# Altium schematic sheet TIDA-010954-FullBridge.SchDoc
size 431 x 279 mm; Date: Not shown in title block; ApprovedBy: Not shown in title block; CheckedBy: Not shown in title block; Author: Not shown in title block; CompanyName: Not shown in title block; Engineer: Not shown in title block; Organization: Not shown in title block; Address1: Not shown in title block; Address2: Not shown in title block; Address3: Not shown in title block; Address4: Not shown in title block; DocumentNumber: 2; Revision: Use project parameter SCH_Rev; SheetNumber: 4; SheetTotal: 9; PageSetup: Record=PageOptions¦CenterHorizontal=True¦CenterVertical=True¦PrintScale=1.00¦XCorrection=1.00¦YCorrection=1.00¦PrintKind=0¦BorderSize=5000000¦LeftOffset=0¦BottomOffset=0¦Orientation=2¦PaperLength=1000¦PaperWidth=1000¦Scale=100¦PaperSource=15¦PrintQuality=600¦MediaType=1¦DitherType=10¦PaperKind=Letter¦PrintScaleMode=1
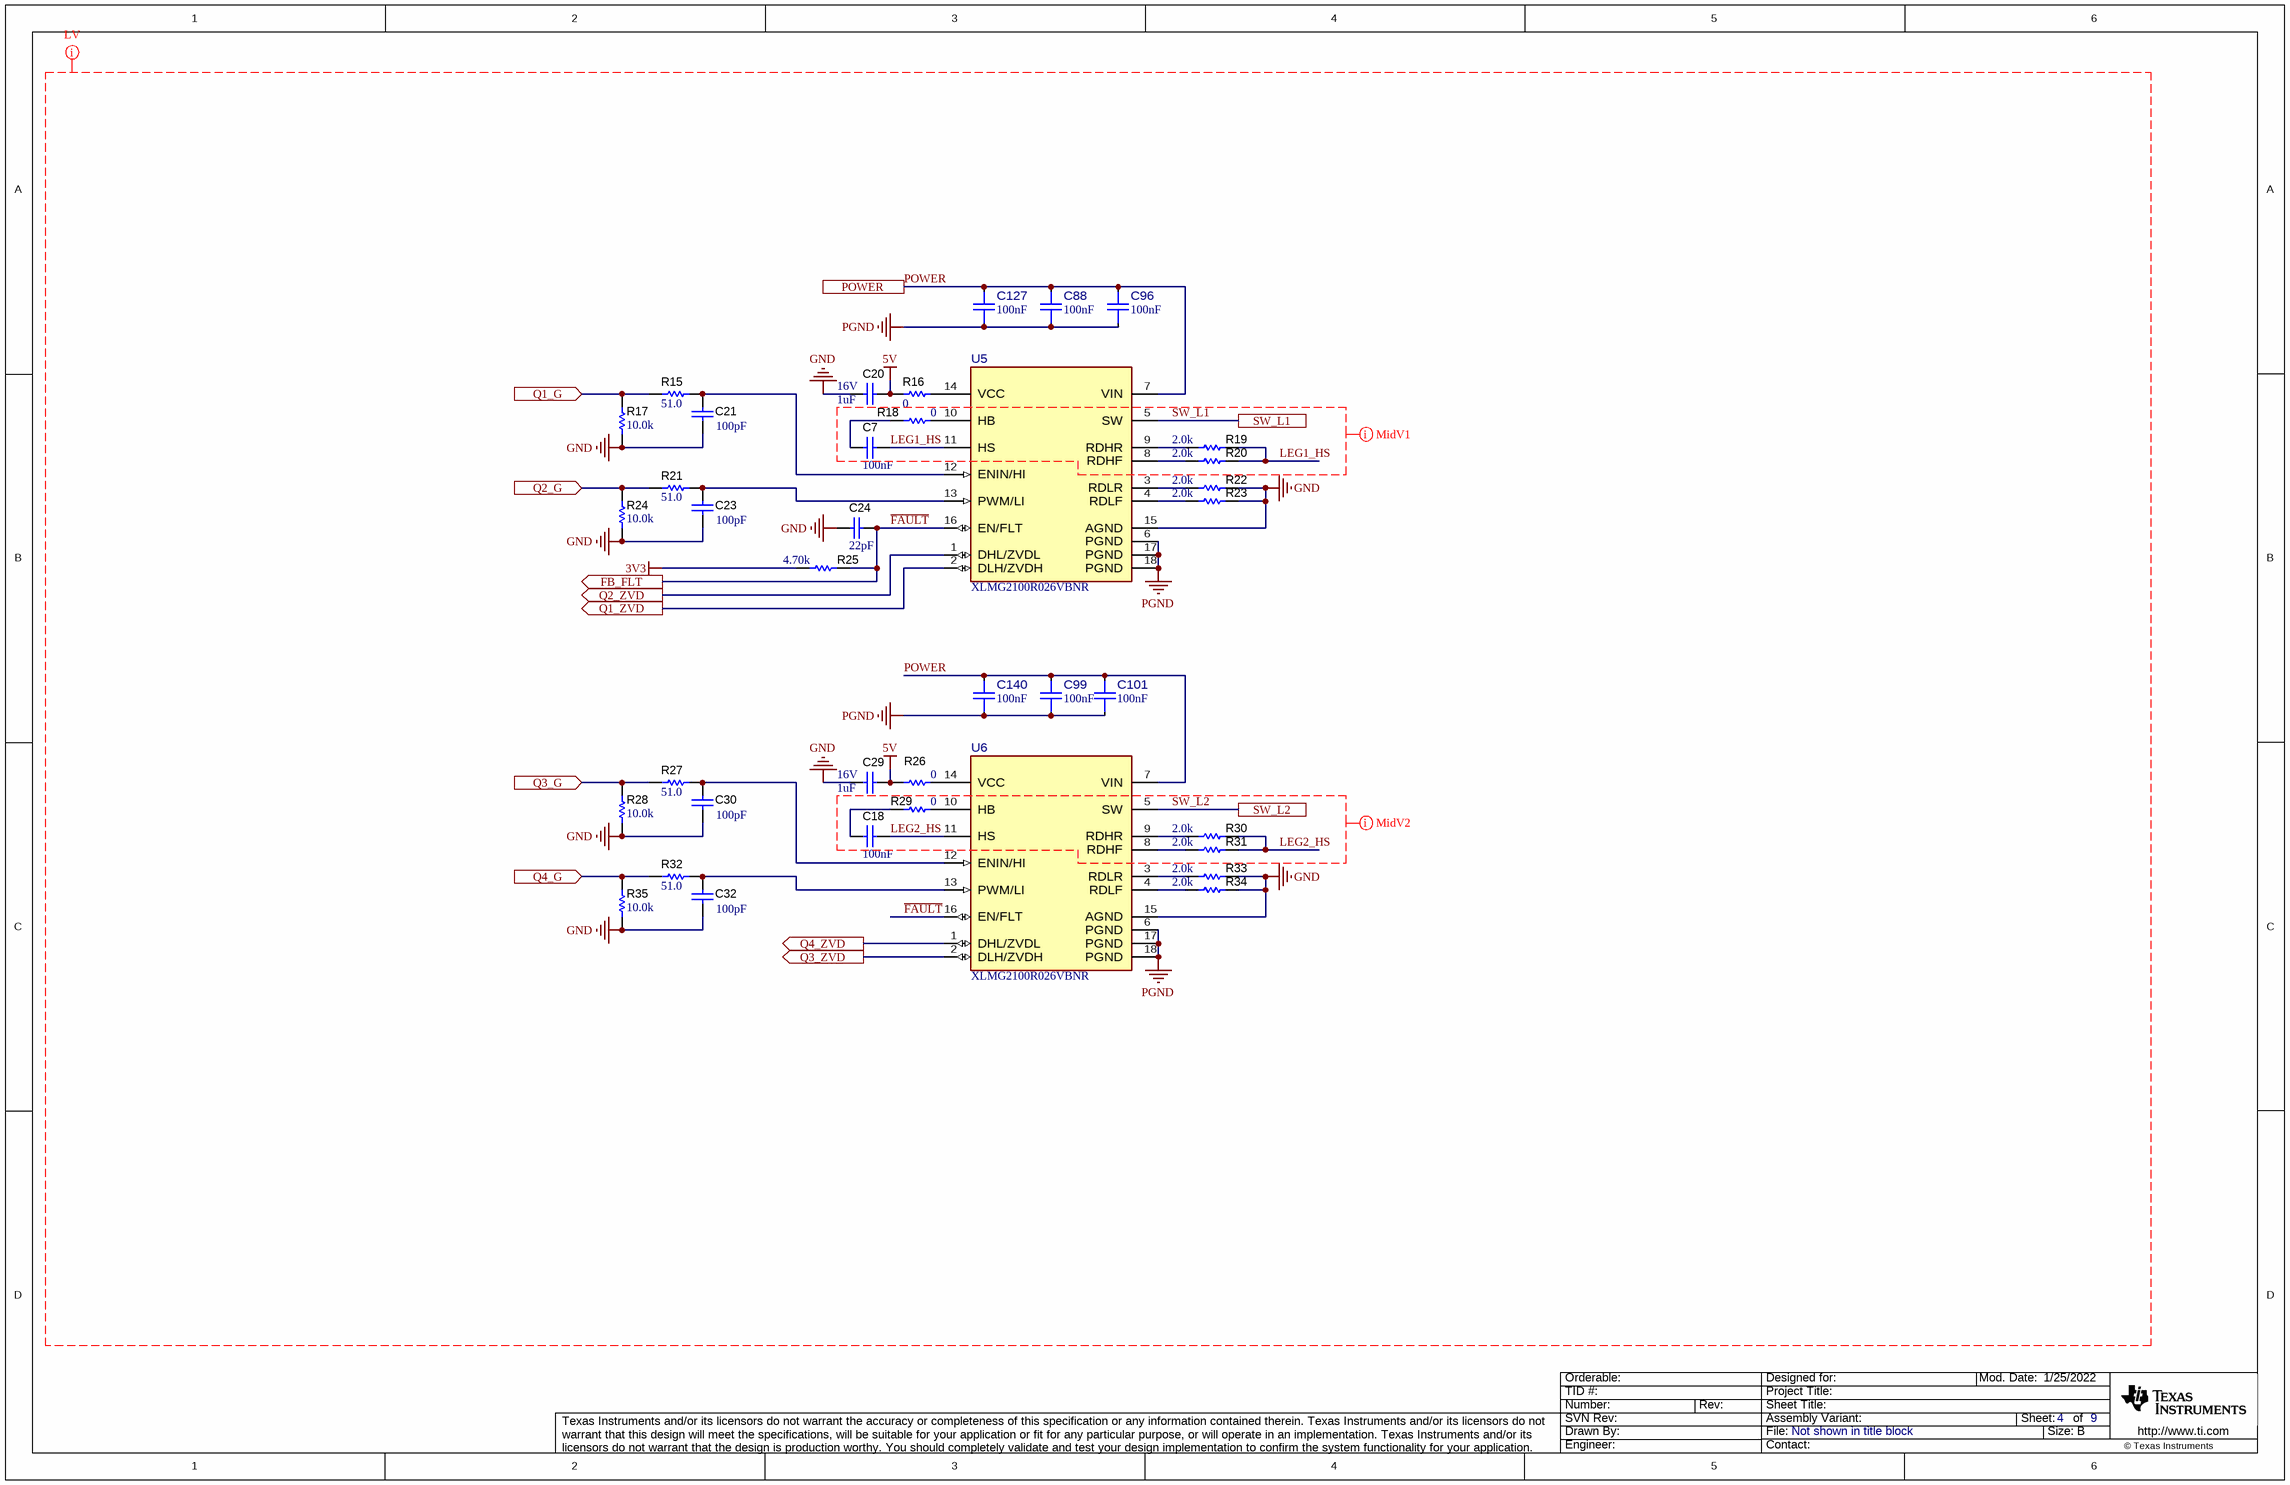
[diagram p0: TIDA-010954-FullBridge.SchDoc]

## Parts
C7  Cap_F: 100nF  [0603]  (hidden comment: CGA3E2X7R1E104K080AA)
C18  Cap_F: 100nF  [0603]  (hidden comment: CGA3E2X7R1E104K080AA)
C20  VDC_V: 16V  ValueDisplayed: 1uF  [0603]  (hidden comment: GRM185R61C105KE44D)
C21  ValueDisplayed: 100pF  [0603]  (hidden comment: GRM1885C1H101JA01D)
C23  ValueDisplayed: 100pF  [0603]  (hidden comment: GRM1885C1H101JA01D)
C24  ValueDisplayed: 22pF  [0603]  (hidden comment: GRM1885C1H220JA01D)
C29  VDC_V: 16V  ValueDisplayed: 1uF  [0603]  (hidden comment: GRM185R61C105KE44D)
C30  ValueDisplayed: 100pF  [0603]  (hidden comment: GRM1885C1H101JA01D)
C32  ValueDisplayed: 100pF  [0603]  (hidden comment: GRM1885C1H101JA01D)
C88  Cap_F: 100nF  [FP-GRM188R72A104KA35J_0603-MFG]  (hidden comment: GRM188R72A104KA35J)
C96  Cap_F: 100nF  [FP-GRM188R72A104KA35J_0603-MFG]  (hidden comment: GRM188R72A104KA35J)
C99  Cap_F: 100nF  [FP-GRM188R72A104KA35J_0603-MFG]  (hidden comment: GRM188R72A104KA35J)
C101  Cap_F: 100nF  [FP-GRM188R72A104KA35J_0603-MFG]  (hidden comment: GRM188R72A104KA35J)
C127  Cap_F: 100nF  [FP-GRM188R72A104KA35J_0603-MFG]  (hidden comment: GRM188R72A104KA35J)
C140  Cap_F: 100nF  [FP-GRM188R72A104KA35J_0603-MFG]  (hidden comment: GRM188R72A104KA35J)
R15  ValueDisplayed: 51.0  [0603]  (hidden comment: RC0603FR-0751RL)
R16  ValueDisplayed: 0  [0603]  (hidden comment: RC0603JR-070RL)
R17  ValueDisplayed: 10.0k  [0603]  (hidden comment: RC0603FR-0710KL)
R18  ValueDisplayed: 0  [0603]  (hidden comment: RC0603JR-070RL)
R19  ValueDisplayed: 2.0k  [0603]  (hidden comment: RC0603JR-072KL)
R20  ValueDisplayed: 2.0k  [0603]  (hidden comment: RC0603JR-072KL)
R21  ValueDisplayed: 51.0  [0603]  (hidden comment: RC0603FR-0751RL)
R22  ValueDisplayed: 2.0k  [0603]  (hidden comment: RC0603JR-072KL)
R23  ValueDisplayed: 2.0k  [0603]  (hidden comment: RC0603JR-072KL)
R24  ValueDisplayed: 10.0k  [0603]  (hidden comment: RC0603FR-0710KL)
R25  ValueDisplayed: 4.70k  [0603]  (hidden comment: RC0603FR-074K7L)
R26  ValueDisplayed: 0  [0603]  (hidden comment: RC0603JR-070RL)
R27  ValueDisplayed: 51.0  [0603]  (hidden comment: RC0603FR-0751RL)
R28  ValueDisplayed: 10.0k  [0603]  (hidden comment: RC0603FR-0710KL)
R29  ValueDisplayed: 0  [0603]  (hidden comment: RC0603JR-070RL)
R30  ValueDisplayed: 2.0k  [0603]  (hidden comment: RC0603JR-072KL)
R31  ValueDisplayed: 2.0k  [0603]  (hidden comment: RC0603JR-072KL)
R32  ValueDisplayed: 51.0  [0603]  (hidden comment: RC0603FR-0751RL)
R33  ValueDisplayed: 2.0k  [0603]  (hidden comment: RC0603JR-072KL)
R34  ValueDisplayed: 2.0k  [0603]  (hidden comment: RC0603JR-072KL)
R35  ValueDisplayed: 10.0k  [0603]  (hidden comment: RC0603FR-0710KL)
U5  XLMG2100R026VBNR  [VBN0018A-MFG]
U6  XLMG2100R026VBNR  [VBN0018A-MFG]

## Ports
FB_FLT (out), POWER, Q1_G (in), Q1_ZVD (out), Q2_G (in), Q2_ZVD (out), Q3_G (in), Q3_ZVD (out), Q4_G (in), Q4_ZVD (out), SW_L1, SW_L2

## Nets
3V3: R25.1
5V: C20.2 C29.2 R16.1 R26.1
GND: C20.1 C21.2 C23.2 C24.1 C29.1 C30.2 C32.2 R17.1 R22.2 R23.2 R24.1 R28.1 R33.2 R34.2 R35.1 U5.15(AGND) U6.15(AGND)
PGND: C88.1 C96.1 C99.1 C101.1 C127.1 C140.1 U5.6(PGND) U5.17(PGND) U5.18(PGND) U6.6(PGND) U6.17(PGND) U6.18(PGND)
~{FAULT}: C24.2 R25.2 U5.16(EN/FLT) U6.16(EN/FLT) ; port FB_FLT
LEG1_HS: C7.2 R19.2 R20.2 U5.11(HS)
LEG2_HS: C18.2 R30.2 R31.2 U6.11(HS)
POWER: C88.2 C96.2 C99.2 C101.2 C127.2 C140.2 U5.7(VIN) U6.7(VIN) ; port POWER
Q1_G: R15.1 R17.2 ; port Q1_G
Q1_ZVD: U5.2(DLH/ZVDH) ; port Q1_ZVD
Q2_G: R21.1 R24.2 ; port Q2_G
Q2_ZVD: U5.1(DHL/ZVDL) ; port Q2_ZVD
Q3_G: R27.1 R28.2 ; port Q3_G
Q3_ZVD: U6.2(DLH/ZVDH) ; port Q3_ZVD
Q4_G: R32.1 R35.2 ; port Q4_G
Q4_ZVD: U6.1(DHL/ZVDL) ; port Q4_ZVD
SW_L1: U5.5(SW) ; port SW_L1
SW_L2: U6.5(SW) ; port SW_L2
NetC7_1: C7.1 R18.1
NetC18_1: C18.1 R29.1
NetC21_1: C21.1 R15.2 U5.12(ENIN/HI)
NetC23_1: C23.1 R21.2 U5.13(PWM/LI)
NetC30_1: C30.1 R27.2 U6.12(ENIN/HI)
NetC32_1: C32.1 R32.2 U6.13(PWM/LI)
NetR16_2: R16.2 U5.14(VCC)
NetR18_2: R18.2 U5.10(HB)
NetR19_1: R19.1 U5.9(RDHR)
NetR20_1: R20.1 U5.8(RDHF)
NetR22_1: R22.1 U5.3(RDLR)
NetR23_1: R23.1 U5.4(RDLF)
NetR26_2: R26.2 U6.14(VCC)
NetR29_2: R29.2 U6.10(HB)
NetR30_1: R30.1 U6.9(RDHR)
NetR31_1: R31.1 U6.8(RDHF)
NetR33_1: R33.1 U6.3(RDLR)
NetR34_1: R34.1 U6.4(RDLF)

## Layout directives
net class MidV1: LEG1_HS, SW_L1
net class MidV2: LEG2_HS, SW_L2
net class LV: 3V3, 5V, GND, LEG1_HS, LEG2_HS, PGND, POWER, SW_L1, SW_L2, ~{FAULT}

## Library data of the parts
C7 C18 = CMP-0007077-5: CAP, CERM, 0.1 uF, 25 V, +/- 10%, X7R, AEC-Q200 Grade 1, 0603; Manufacturer: TDK; TaMin_C: -55°C; Polarized: N; SizeAreaWB_mm2: 4.68; Value1: Unknown; U/M: EA; Value: 0.1uF; TaMax_C: 125°C; SizeZ_mm: 1; SizeX_mm: 1.6; SizeY_mm: 0.8; Value2: 25V; SizeArea_mm2: 1.28; AEC Qualified: Y; AEC Category: Q200
C20 C29 = CMP-0007157-5: CAP, CERM, 1 uF, 16 V, +/- 10%, X5R, 0603; Manufacturer: MuRata; TaMin_C: -55°C; Polarized: N; SizeAreaWB_mm2: 4.68; Value1: Unknown; U/M: EA; Value: 1uF; TaMax_C: 85°C; SizeZ_mm: 1; SizeX_mm: 1.6; SizeY_mm: 0.8; SizeArea_mm2: 1.28; Cap_F: 1µF; AEC Category: Q200
C21 C23 C30 C32 = CMP-0007171-4: CAP, CERM, 100 pF, 50 V, +/- 5%, C0G/NP0, 0603; Manufacturer: MuRata; TaMin_C: -55°C; Polarized: N; SizeAreaWB_mm2: 4.68; Value1: Unknown; U/M: EA; Value: 100pF; TaMax_C: 125°C; SizeZ_mm: 1; SizeX_mm: 1.6; SizeY_mm: 0.8; Value2: 50V; SizeArea_mm2: 1.28; AEC Category: Q200
C24 = CMP-0007196-4: CAP, CERM, 22 pF, 50 V, +/- 5%, C0G/NP0, 0603; Manufacturer: MuRata; TaMin_C: -55°C; Polarized: N; SizeAreaWB_mm2: 4.68; Value1: Unknown; U/M: EA; Value: 22pF; TaMax_C: 125°C; SizeZ_mm: 1; SizeX_mm: 1.6; SizeY_mm: 0.8; Value2: 50V; SizeArea_mm2: 1.28; AEC Category: Q200
C88 C96 C99 C101 C127 C140 = CMP-0122713-1: Chip Multilayer Ceramic Capacitors for General Purpose, 0603, 0.10uF, X7R, 15%, 10%, 100V; Manufacturer: Murata; AEC Qualified: No; SizeZ_mm: 0.9mm; Value: 100nF
R15 R21 R27 R32 = CMP-0023169-5: RES, 51.0, 1%, 0.1 W, 0603; Manufacturer: Yageo; Power_W: 100mW; TempCo: 100 ppm/C; Value_Code: 51R0; Value: 51.0; Res_ohm: 51; SizeX_mm: 1.6; SizeY_mm: 0.8; SizeZ_mm: 1; Value2: 0.1W; SizeArea_mm2: 1.28; AEC Qualified: N; VDC_V: 75V; AEC Category: Q200; SizeAreaWB_mm2: 4.68
R16 R18 R26 R29 = CMP-0025885-5: RES, 0, 5%, 0.1 W, 0603; Manufacturer: Yageo; Power_W: 100mW; TempCo: 200 ppm/C; Value_Code: 0000; Value: 0; EIA_Code: E24; SizeX_mm: 1.6; SizeZ_mm: 1; Value2: 0.1W; SizeArea_mm2: 1.28; AEC Qualified: N; VDC_V: 75V; AEC Category: Q200; SizeY_mm: 0.8; SizeAreaWB_mm2: 4.68
R17 R24 R28 R35 = CMP-0022746-5: RES, 10.0 k, 1%, 0.1 W, 0603; Manufacturer: Yageo; Power_W: 100mW; TempCo: 100 ppm/C; Value_Code: 10k0; Value: 10.0k; EIA_Code: E96; Res_ohm: 10k; SizeX_mm: 1.6; SizeY_mm: 0.8; SizeZ_mm: 1; Value2: 0.1W; SizeArea_mm2: 1.28; AEC Qualified: N; VDC_V: 75V; AEC Category: Q200; SizeAreaWB_mm2: 4.68
R19 R20 R22 R23 R30 R31 R33 R34 = CMP-0025909-5: RES, 2.0 k, 5%, 0.1 W, 0603; Manufacturer: Yageo; Power_W: 100mW; TempCo: 100 ppm/C; Value_Code: 2k00; Value: 2.0k; EIA_Code: E24; Res_ohm: 2k; SizeX_mm: 1.6; SizeY_mm: 0.8; SizeZ_mm: 1; Value2: 0.1W; SizeArea_mm2: 1.28; AEC Qualified: N; VDC_V: 75V; AEC Category: Q200; SizeAreaWB_mm2: 4.68
R25 = CMP-0023153-5: RES, 4.70 k, 1%, 0.1 W, 0603; Manufacturer: Yageo; Power_W: 100mW; TempCo: 100 ppm/C; Value_Code: 4k70; Value: 4.70k; Res_ohm: 4.7k; SizeX_mm: 1.6; SizeY_mm: 0.8; SizeZ_mm: 1; Value2: 0.1W; SizeArea_mm2: 1.28; AEC Qualified: N; VDC_V: 75V; AEC Category: Q200; SizeAreaWB_mm2: 4.68
U5 U6 = CMP-0122483-1: 170-V GaN Half-Bridge Power Stages; Manufacturer: Texas Instruments; Part Number: LMG2175; SizeZ_mm: 0.85mm; AEC Qualified: No; Max Supply Voltage: 5.5V; Min Supply Voltage: 4.5V; Nominal Supply Current: 8.5mA; Number Of Outputs: 1; Standoff Height: 0mm; TJmax_C: +150°C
